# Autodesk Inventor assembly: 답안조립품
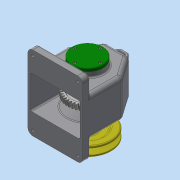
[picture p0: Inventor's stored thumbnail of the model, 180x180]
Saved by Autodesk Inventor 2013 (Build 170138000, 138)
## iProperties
Created: 2016-12
Part Number: 답안조립품
Document SubType Name: Assembly
Designer: dgall
Author: dgall
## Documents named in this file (15)
- C:\Users\dgall\Desktop\461207V1011\답안조립품.iam
- C:\Users\dgall\Desktop\461207V1011\V-벨트풀리.ipt
- C:\Users\dgall\Desktop\461207V1011\뒤커버.ipt
- C:\Users\dgall\Desktop\461207V1011\멈춤나사 - M4x10.ipt
- C:\Users\dgall\Desktop\461207V1011\베어링 6203.ipt
- C:\Users\dgall\Desktop\461207V1011\본체.ipt
- C:\Users\dgall\Desktop\461207V1011\볼트 M3 x 8.ipt
- C:\Users\dgall\Desktop\461207V1011\볼트 M3 x 10.ipt
- C:\Users\dgall\Desktop\461207V1011\부시.ipt
- C:\Users\dgall\Desktop\461207V1011\스퍼기어.ipt
- C:\Users\dgall\Desktop\461207V1011\앞커버.ipt
- C:\Users\dgall\Desktop\461207V1011\오일씰 28 40 8.ipt
- C:\Users\dgall\Desktop\461207V1011\축.ipt
- C:\Users\dgall\Desktop\461207V1011\키 - 5 x 5 x 18.ipt
- C:\Users\dgall\Desktop\461207V1011\키 - 6 x 6 x 22.ipt
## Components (9 placed, 3 different names)
1. V-벨트풀리:1 — 각도:4
2. ISO 4762 M3 x 10:1
3. ISO 4762 M3 x 10:2
4. ISO 4762 M3 x 10:3
5. ISO 4762 M3 x 10:4
6. ISO 4762 M3 x 8:1
7. ISO 4762 M3 x 8:2
8. ISO 4762 M3 x 8:3
9. ISO 4762 M3 x 8:4
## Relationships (1: Angle 1)
- 각도:4 [Angle]: V-벨트풀리:1
